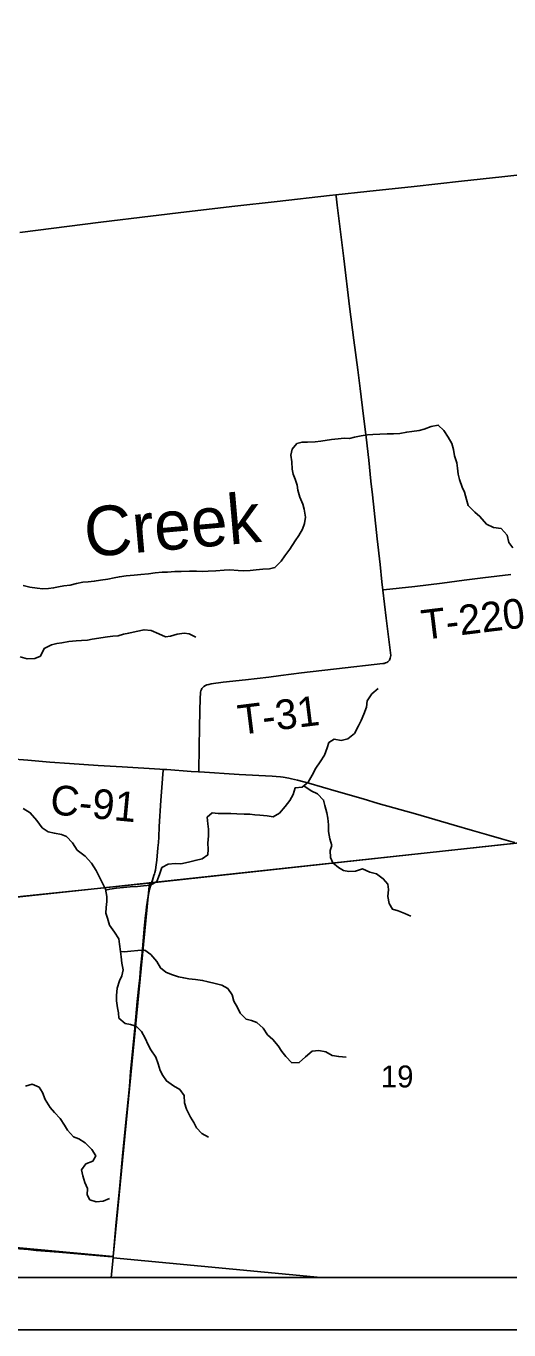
# Model space of a CAD drawing. Extents: x 0 to 34, y -5.4 to 22.
# Drawn here: x 3.809 to 4.732, y 14 to 16.492 of the extents above; entities that cross this region are included whole.
import ezdxf

# ---------------------------------------------------------------- set-up
doc = ezdxf.new("R2010")
doc.units = 0
for name, color, linetype in [('Default', 7, 'Continuous'), ('GM_X_County_Road', 7, 'Continuous'), ('GM_X_County_Road_Text', 7, 'Continuous'), ('GM_X_Minor_River', 7, 'Continuous'), ('GM_X_Minor_River_Text', 7, 'Continuous'), ('GM_X_Rail_Line', 7, 'Continuous'), ('GM_X_Section', 7, 'Continuous'), ('GM_X_Section_Text', 7, 'Continuous'), ('GM_X_Township_Road', 7, 'Continuous'), ('GM_X_Township_Road_Text', 7, 'Continuous'), ('SH_Data', 7, 'Continuous')]:
    doc.layers.add(name, color=color, linetype=linetype)

msp = doc.modelspace()

# ---------------------------------------------------------------- linework, layer by layer
at = {"layer": 'Default'}
for points in [[(4.3725, 14.1), (4.9934, 14.1), (5.0709, 14.9656), (4.0448, 14.8547), (3.9754, 14.1403), (3.9753, 14.1377)], [(2.9585, 14.1), (3.9718, 14.1), (3.9753, 14.1377), (3.9754, 14.1403), (2.9696, 14.2333)], [(3.9718, 14.1), (4.3725, 14.1), (3.9753, 14.1377)]]:
    msp.add_lwpolyline(points, close=True, dxfattribs=at)
at = {"layer": 'GM_X_County_Road'}
for points in [[(3.7969, 16.0976), (3.9522, 16.1174), (4.0472, 16.129), (4.1157, 16.137), (4.2083, 16.1482), (4.2892, 16.1571), (4.3893, 16.1683), (4.4011, 16.1696), (4.4603, 16.1761), (4.5511, 16.1858), (4.6413, 16.1957), (4.7185, 16.204), (4.7926, 16.2124)], [(3.0588, 15.1461), (3.0761, 15.1449), (3.1226, 15.1417), (3.1796, 15.1377), (3.2286, 15.1343), (3.2695, 15.1315), (3.3241, 15.1279), (3.4127, 15.1221), (3.4983, 15.1162), (3.5785, 15.1102), (3.5913, 15.1092), (3.6065, 15.1081), (3.6608, 15.1033), (3.6903, 15.1005), (3.7286, 15.0967), (3.7787, 15.0919), (3.8127, 15.0888), (3.8542, 15.0853), (3.892, 15.0828), (3.9472, 15.0791), (3.9927, 15.0764), (4.065, 15.0719), (4.0712, 15.0715)], [(4.0712, 15.0715), (4.0784, 15.0712), (4.1245, 15.0675), (4.1389, 15.0666)], [(4.1389, 15.0666), (4.1408, 15.0665), (4.2163, 15.0618), (4.2796, 15.0583), (4.2872, 15.0578), (4.2953, 15.057), (4.3007, 15.0563), (4.3111, 15.0546), (4.3164, 15.0536), (4.3278, 15.0509), (4.3494, 15.0449), (4.4019, 15.0297), (4.4532, 15.015), (4.4818, 15.0065), (4.5533, 14.9862), (4.6276, 14.9647), (4.6623, 14.9545), (4.6939, 14.9458), (4.718, 14.9389), (4.7356, 14.9337), (4.7431, 14.9314)]]:
    msp.add_lwpolyline(points, dxfattribs=at)
at = {"layer": 'GM_X_Minor_River'}
for points in [[(4.3197, 15.6354), (4.318, 15.6453), (4.3171, 15.659), (4.3154, 15.6723), (4.3179, 15.6836), (4.3268, 15.6945), (4.3366, 15.697), (4.3472, 15.6968), (4.3616, 15.6977), (4.3726, 15.699), (4.3931, 15.7017), (4.4056, 15.703), (4.4174, 15.7044), (4.4272, 15.7042), (4.4371, 15.7067), (4.4496, 15.7091), (4.4617, 15.7108), (4.472, 15.7118), (4.4852, 15.7123), (4.4992, 15.7125), (4.5113, 15.7126), (4.5235, 15.7136), (4.5368, 15.716), (4.5466, 15.7174), (4.5603, 15.7194), (4.5698, 15.7219), (4.5835, 15.7266), (4.5968, 15.7294), (4.6079, 15.7194), (4.6161, 15.7067), (4.623, 15.6941), (4.6259, 15.683), (4.6283, 15.6708), (4.6323, 15.6571), (4.634, 15.6472), (4.6349, 15.6358), (4.6378, 15.6255), (4.6429, 15.611), (4.6469, 15.6011), (4.6508, 15.587), (4.654, 15.5759), (4.6667, 15.5632), (4.6767, 15.5551), (4.6894, 15.5404), (4.7025, 15.5338), (4.7172, 15.5316), (4.7284, 15.5193), (4.7319, 15.5048), (4.7393, 15.4948)], [(3.8034, 15.4226), (3.8166, 15.4198), (3.8306, 15.4176), (3.8412, 15.4167), (3.8522, 15.4169), (3.8616, 15.4182), (3.8711, 15.4203), (3.8814, 15.4221), (3.8931, 15.4238), (3.9057, 15.427), (3.9174, 15.429), (3.928, 15.4296), (3.9394, 15.4309), (3.9516, 15.433), (3.9652, 15.4351), (3.9774, 15.4375), (3.9876, 15.4396), (4.0005, 15.4417), (4.0157, 15.4429), (4.0286, 15.4438), (4.0434, 15.4455), (4.0559, 15.4468), (4.0691, 15.4481), (4.0797, 15.4487), (4.0937, 15.4496), (4.1055, 15.4497), (4.1214, 15.4502), (4.135, 15.4504), (4.1456, 15.4498), (4.157, 15.4504), (4.1717, 15.4509), (4.1876, 15.4522), (4.1986, 15.4527), (4.2145, 15.4513), (4.2243, 15.4511), (4.2372, 15.4513), (4.2486, 15.4526), (4.2615, 15.4539), (4.2743, 15.4549), (4.2846, 15.457), (4.2965, 15.4693), (4.3035, 15.4798), (4.3132, 15.4925), (4.3233, 15.5083), (4.3303, 15.5184), (4.3373, 15.5308), (4.3412, 15.5414), (4.3433, 15.5535), (4.3409, 15.5691), (4.3381, 15.5786), (4.3322, 15.592), (4.3283, 15.6053), (4.327, 15.6148), (4.3237, 15.6259), (4.3197, 15.6354)], [(3.7978, 15.2866), (3.8109, 15.2825), (3.8261, 15.2834), (3.8364, 15.2878), (3.8434, 15.3028), (3.8575, 15.3094), (3.8678, 15.3119), (3.8773, 15.3133), (3.891, 15.3161), (3.905, 15.317), (3.9152, 15.3176), (3.9262, 15.3185), (3.9357, 15.3206), (3.9645, 15.3247), (3.9751, 15.326), (3.9854, 15.327), (3.9956, 15.3298), (4.0055, 15.332), (4.0196, 15.3351), (4.0348, 15.3383), (4.048, 15.3369), (4.063, 15.3302), (4.0754, 15.3251), (4.0853, 15.326), (4.0978, 15.3296), (4.1111, 15.3317), (4.1209, 15.3308), (4.1333, 15.3241)], [(3.961, 14.8405), (3.9689, 14.8425), (3.9818, 14.8442), (3.9951, 14.8455), (4.008, 14.8468), (4.022, 14.8473), (4.0334, 14.8486), (4.047, 14.8503), (4.0592, 14.8569), (4.0644, 14.8708), (4.0688, 14.8837), (4.081, 14.8903), (4.0939, 14.8912), (4.1052, 14.891), (4.1193, 14.8938), (4.1322, 14.8974), (4.1455, 14.9002), (4.1562, 14.908), (4.1571, 14.9186), (4.1566, 14.9303), (4.158, 14.9444), (4.1578, 14.9573), (4.1568, 14.9675), (4.1555, 14.9801), (4.1651, 14.9882), (4.1761, 14.9873), (4.1905, 14.987), (4.2003, 14.9873), (4.212, 14.9863), (4.226, 14.9861), (4.2366, 14.9859), (4.2464, 14.9846), (4.2562, 14.9836), (4.2702, 14.9827), (4.2812, 14.981), (4.2934, 14.9876), (4.3046, 15.0003), (4.3131, 15.0119), (4.3194, 15.0232), (4.3237, 15.0364), (4.3366, 15.0373), (4.3481, 15.047), (4.3559, 15.0601), (4.363, 15.074), (4.3715, 15.0856), (4.3793, 15.0988), (4.3844, 15.1127), (4.3876, 15.1225), (4.3979, 15.1292), (4.4115, 15.1267), (4.4244, 15.1295), (4.4367, 15.1403), (4.4445, 15.1549), (4.4496, 15.1651), (4.4547, 15.1772), (4.4595, 15.1903), (4.4612, 15.2025), (4.4701, 15.2156), (4.4821, 15.226)], [(4.34, 15.0401), (4.3539, 15.0302), (4.3659, 15.0247), (4.3778, 15.0127), (4.3803, 15.0024), (4.3842, 14.9883), (4.386, 14.9784), (4.3869, 14.9655), (4.3874, 14.9526), (4.3898, 14.9389), (4.3934, 14.9259), (4.3906, 14.9161), (4.3908, 14.9032), (4.3955, 14.8925), (4.4063, 14.884), (4.4161, 14.8781), (4.4262, 14.8761), (4.4387, 14.8766), (4.4521, 14.8813), (4.466, 14.875), (4.4788, 14.8718), (4.4919, 14.8624), (4.5008, 14.8517), (4.5017, 14.8418), (4.5008, 14.8282), (4.5028, 14.8152), (4.5094, 14.8045), (4.52, 14.8013), (4.5328, 14.7958), (4.5444, 14.7906)], [(3.8035, 14.9967), (3.817, 14.9885), (3.8296, 14.9735), (3.84, 14.9596), (3.8512, 14.9522), (3.8633, 14.9494), (3.8768, 14.9469), (3.8866, 14.9433), (3.8978, 14.931), (3.9066, 14.9172), (3.9219, 14.9055), (3.9342, 14.8924), (3.943, 14.8782), (3.9496, 14.8656), (3.9559, 14.8526), (3.9606, 14.8423), (3.9634, 14.8286), (3.9636, 14.8191), (3.9619, 14.8074), (3.9614, 14.7967), (3.9646, 14.7872), (3.9685, 14.7739), (3.9778, 14.7604), (3.9863, 14.7474), (3.9876, 14.7371), (3.9893, 14.7234), (3.9906, 14.7128), (3.9919, 14.701), (3.9944, 14.6885), (3.9923, 14.6767), (3.9879, 14.667), (3.9832, 14.653), (3.9818, 14.639), (3.982, 14.6291), (3.984, 14.6158), (3.9858, 14.6059), (3.9867, 14.5961), (3.9987, 14.5856), (4.0085, 14.5835), (4.0194, 14.5803), (4.0295, 14.5707), (4.0368, 14.5576), (4.0426, 14.5447), (4.0478, 14.5351), (4.0574, 14.5216), (4.0617, 14.5087), (4.0657, 14.4957), (4.0708, 14.4861), (4.0774, 14.4758), (4.0909, 14.4665), (4.1029, 14.4598), (4.111, 14.4479), (4.1116, 14.4339), (4.1159, 14.4217), (4.1236, 14.4067), (4.1298, 14.3964), (4.135, 14.3861), (4.145, 14.3753), (4.1578, 14.3682)], [(3.9893, 14.723), (3.9968, 14.7226), (4.0093, 14.7239), (4.023, 14.7255), (4.0358, 14.7257), (4.0478, 14.7175), (4.059, 14.7044), (4.0663, 14.6918), (4.076, 14.6837), (4.0873, 14.6793), (4.1005, 14.6749), (4.1106, 14.6728), (4.1205, 14.6711), (4.1329, 14.6698), (4.1465, 14.668), (4.1571, 14.6652), (4.1703, 14.6623), (4.1834, 14.6591), (4.1947, 14.6528), (4.2028, 14.6405), (4.2064, 14.6283), (4.2134, 14.6161), (4.2185, 14.6054), (4.2297, 14.5938), (4.2398, 14.5917), (4.25, 14.5878), (4.2623, 14.5769), (4.2704, 14.5643), (4.2809, 14.5554), (4.2909, 14.5431), (4.2979, 14.5323), (4.3057, 14.5227), (4.3172, 14.5108), (4.3312, 14.5109), (4.3431, 14.5217), (4.3558, 14.5329), (4.3687, 14.5338), (4.3822, 14.5313), (4.3942, 14.5246), (4.4067, 14.5225), (4.4211, 14.5211)], [(3.8082, 14.4656), (3.8208, 14.4699), (3.8339, 14.464), (3.8405, 14.4537), (3.8453, 14.4407), (3.8552, 14.4253), (3.8634, 14.4157), (3.8742, 14.4042), (3.8823, 14.3915), (3.8882, 14.3815), (3.8997, 14.3688), (3.9098, 14.3652), (3.9222, 14.3575), (3.9345, 14.3451), (3.9422, 14.3328), (3.9364, 14.3227), (3.9234, 14.3172), (3.9153, 14.306), (3.9173, 14.2946), (3.9217, 14.282), (3.9264, 14.2705), (3.9258, 14.2584), (3.931, 14.2488), (3.943, 14.2445), (3.9563, 14.2461), (3.9685, 14.2512)]]:
    msp.add_lwpolyline(points, dxfattribs=at)
at = {"layer": 'GM_X_Rail_Line'}
msp.add_lwpolyline([(3.2432, 17.2942), (3.13, 16.1326), (3.0967, 15.7517), (3.0382, 15.1455), (3.0059, 14.7462), (4.0439, 14.8538), (4.7395, 14.9295)], dxfattribs=at)
msp.add_lwpolyline([(2.9527, 14.1), (8.0559, 14.1), (8.0925, 14.4946), (8.0933, 14.5029), (8.1066, 14.6429), (8.1702, 15.3079), (7.8983, 15.2739), (7.8942, 15.2734), (7.6929, 15.2483), (7.6796, 15.247), (7.3134, 15.2082), (7.0389, 15.1799), (6.9914, 15.1749), (6.9348, 15.169), (6.9294, 15.1684), (6.92, 15.1674), (6.4463, 15.1177), (6.4403, 15.1171), (6.1164, 15.0793), (4.8765, 14.9444), (4.7395, 14.9295), (4.0439, 14.8538), (3.0059, 14.7462), (2.9641, 14.2324)], close=True, dxfattribs=at)
at = {"layer": 'GM_X_Section'}
msp.add_lwpolyline([(4.0448, 14.8547), (3.9754, 14.1403), (2.9696, 14.2333), (3.0111, 14.744), (3.928, 14.842)], close=True, dxfattribs=at)
at = {"layer": 'GM_X_Township_Road'}
for points in [[(4.1389, 15.0666), (4.139, 15.0699), (4.1401, 15.1121), (4.1409, 15.1543), (4.1414, 15.1804), (4.142, 15.2102), (4.1423, 15.2144), (4.1427, 15.219), (4.1434, 15.2217), (4.1442, 15.224), (4.1453, 15.226), (4.1469, 15.2281), (4.1491, 15.23), (4.1522, 15.2317), (4.1547, 15.2328), (4.1583, 15.2338), (4.163, 15.2347), (4.1858, 15.2379), (4.2284, 15.2426), (4.2728, 15.248), (4.2962, 15.2509), (4.3356, 15.256), (4.4189, 15.2658), (4.4745, 15.2719), (4.4908, 15.2737), (4.4936, 15.2741), (4.4963, 15.2748), (4.4986, 15.2758), (4.5007, 15.277), (4.5025, 15.2786), (4.5037, 15.2803), (4.5045, 15.2818), (4.5053, 15.284), (4.5058, 15.2865), (4.5062, 15.2892), (4.5059, 15.2941), (4.5053, 15.2991), (4.4974, 15.3606), (4.4911, 15.4143), (4.4894, 15.4302), (4.4858, 15.4631), (4.4803, 15.5119), (4.4744, 15.5662), (4.4711, 15.5965), (4.4682, 15.6224), (4.464, 15.6625), (4.4591, 15.7064), (4.4543, 15.7464), (4.4478, 15.7994), (4.4432, 15.8351), (4.4357, 15.8918), (4.4276, 15.9559), (4.4163, 16.0477), (4.4036, 16.1501), (4.4015, 16.1671), (4.4011, 16.1696)], [(4.4911, 15.4143), (4.4925, 15.4145), (4.5519, 15.4211), (4.6043, 15.4276), (4.6462, 15.4329), (4.6819, 15.4375), (4.7356, 15.4439)], [(4.0619, 14.9317), (4.0626, 14.9419), (4.0638, 14.9624), (4.0668, 15.0118), (4.0701, 15.0536), (4.0707, 15.0626), (4.0711, 15.0689), (4.0712, 15.0715)], [(4.0712, 15.0715), (4.0784, 15.0712), (4.1245, 15.0675), (4.1389, 15.0666)], [(4.0497, 14.8564), (4.051, 14.8599), (4.0536, 14.8684), (4.0545, 14.8715), (4.0552, 14.8742), (4.0562, 14.8789), (4.0572, 14.8845), (4.059, 14.898), (4.0612, 14.9215), (4.0619, 14.9317)], [(3.9718, 14.1), (3.9749, 14.1321), (3.9756, 14.1398), (3.9763, 14.1471), (3.9807, 14.1987), (3.9881, 14.2757), (3.9942, 14.3396), (4.0015, 14.4157), (4.0065, 14.4651), (4.009, 14.493), (4.017, 14.5767), (4.0216, 14.6275), (4.0246, 14.6569), (4.0263, 14.6732), (4.0281, 14.6913), (4.031, 14.7206), (4.0356, 14.7735), (4.0376, 14.7918), (4.0386, 14.8013), (4.0395, 14.8091), (4.0405, 14.8168), (4.0412, 14.8222), (4.0428, 14.8315), (4.0436, 14.8355), (4.0451, 14.8421), (4.047, 14.8481), (4.0488, 14.8535), (4.0497, 14.8564)], [(3.7723, 14.157), (3.8133, 14.1534), (3.8285, 14.152), (3.872, 14.1483), (3.9656, 14.1406), (3.9727, 14.14), (3.9756, 14.1398)]]:
    msp.add_lwpolyline(points, dxfattribs=at)
at = {"layer": 'SH_Data'}
for p, q in [((2.1, 14.1), (8.9, 14.1)), ((2, 14), (9, 14))]:
    msp.add_line(p, q, dxfattribs=at)

# ---------------------------------------------------------------- texts
at = {"layer": 'GM_X_County_Road_Text'}
msp.add_text('C-91', height=0.05682, rotation=354.5599, dxfattribs=at).set_placement((3.8536, 14.986))
at = {"layer": 'GM_X_Minor_River_Text'}
msp.add_text('Creek', height=0.0947, rotation=5.0322, dxfattribs=at).set_placement((3.9242, 15.4769))
at = {"layer": 'GM_X_Section_Text'}
msp.add_text('19', height=0.04186, rotation=0, dxfattribs=at).set_placement((4.4873, 14.4635))
at = {"layer": 'GM_X_Township_Road_Text'}
for s, rotation, p in [('T-220', 6.9531, (4.5682, 15.319)), ('T-31', 7.0814, (4.2174, 15.1373))]:
    msp.add_text(s, height=0.05682, rotation=rotation, dxfattribs=at).set_placement(p)

doc.saveas('drawing.dxf')
